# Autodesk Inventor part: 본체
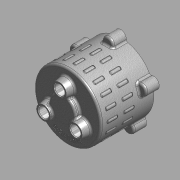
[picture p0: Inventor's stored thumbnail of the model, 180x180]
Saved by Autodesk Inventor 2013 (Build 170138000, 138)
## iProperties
Created: 2015-11
Part Number: 본체
Document SubType Name: 모델링
Designer: mdu
Material: 알루미늄 6061
Density: 1 g/cm^3
변환 표준: STEP AP214IS
파일 이름: C:\Users\SeoGD\Desktop\?쒗뿕\紐몄껜.stp
전처리기: Build: 253, Release: 2010 SP1 - Date: Wed 07/29/2009
전송 단위: 밀리미터
불확실성: 0.01
Author: mdu
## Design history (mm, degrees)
sketch "스케치2"
  geometry: C1 r 50 at (0, 0); 1 further point
  constraints: 1 centre point, 1 coincident
  dimensions: "d9" = 100 diameter of C1
extrude "돌출2" new body sketch "스케치2" distance "d10" = 80; taper "d11" = 0 deg
feature "쉘1" dims "d12" = 5
sketch "스케치3" dims "d13" = 55
  geometry: C1 r 7.5 at (0, 27.5); C2 r 12.5 at (0, 27.5); 2 further points
  constraints: 2 centre point, 2 coincident, 2 vertical alignment, 2 other
  dimensions: "d14" = 15 diameter of C1; "d15" = 25 diameter of C2
extrude "돌출3" join sketch "스케치3" distance "d16" = 12; taper "d17" = -10 deg
hole "구멍2" diameter "d20" = 15; stored, may be unused: countersink angle "d24" = 90 deg, drill point angle "d26" = 118 deg; dims "d18" = 10, "d19" = 10, "d21" = 6, "d22" = 4, "d23" = 2, "d25" = 15
chamfer "모따기1" distance "d27" = 1; stored, may be unused: second distance "d28" = 2, angle "d29" = 45 deg
sketch "스케치4"
  geometry: L1 (0, 0)-(0, 88); L2 (0, 70)-(13.16, 70); L3 (-45, 75)-(45, 75) reference; L4 (-50, 80)-(50, 80) reference; L5 (13.16, 70)-(14.5, 75); L6 (20, 80)-(20, 88); L7 (20, 88)-(0, 88); L8 (20, 80)-(14.5, 75)
  constraints: 12 end point, 3 point on line, 2 perpendicular, 1 vertical
  dimensions: "d34" = 40 diameter of L6 L1; "d35" = 105 deg angle of L5 L3; "d36" = 5 distance between parallel lines of L2 L3; "d37" = 8 distance between parallel lines of L7 L4; "d51" = 29 diameter of L5.end L1
revolve "회전1" sketch "스케치4" stored, may be unused: angle "d38" = 90 deg
hole "구멍3" diameter "d41" = 15; stored, may be unused: countersink angle "d45" = 90 deg, drill point angle "d47" = 0 deg; dims "d39" = 10, "d40" = 10, "d42" = 6, "d43" = 22, "d44" = 13, "d46" = 15
chamfer "모따기2" distance "d48" = 1; stored, may be unused: second distance "d49" = 2, angle "d50" = 45 deg
fillet "모깎기1" dims "d52" = 3
fillet "모깎기2" dims "d53" = 3, "d72" = 0.2
sketch "스케치5"
  geometry: A1 r 50 centre (0, 0) between (50, 0) and (-8.074, 49.344) reference; A2 r 8.5 centre (0, 52) between (8.074, 49.344) and (-8.074, 49.344); 1 further point
  constraints: 5 point on circle, 1 centre point, 1 horizontal alignment
  dimensions: "d54" = 90 deg dimension on point (0, 0) A2.centre A1.start; "d55" = 52 distance of A2.centre point (0, 0); "d56" = 17 diameter of A2
extrude "돌출4" join sketch "스케치5" distance "d57" = 20; taper "d58" = 0 deg
fillet "모깎기3" dims "d59" = 3
hole "구멍4" diameter "d62" = 4.134; stored, may be unused: countersink angle "d66" = 90 deg, drill point angle "d68" = 118 deg; dims "d60" = 10, "d61" = 10, "d63" = 12, "d64" = 22, "d65" = 13, "d67" = 15
sketch "스케치6"
  geometry: C1 r 47 at (0, 0) reference; C2 r 42.5 at (0, 0); 1 further point
  constraints: 1 centre point, 1 coincident, 1 other
  dimensions: "d73" = 85 diameter of C2
feature "엠보싱1" sketch "스케치6" dims "d74" = 0.5, "d75" = 0
node "작업 평면1"
sketch "스케치7"
  geometry: A1 r 50 centre (0, 0) between (5.144, 49.735) and (-5.144, 49.735) reference; A2 r 3 centre (0, 47.916) between (2.204, 49.951) and (-2.204, 49.951); 1 further point
  constraints: 4 point on circle, 1 centre point, 1 vertical alignment
  dimensions: "d77" = 3 radius of A2
extrude "돌출5" join sketch "스케치7" distance "d79" = 15; taper "d80" = 0 deg
fillet "모깎기4" dims "d81" = 1
fillet "모깎기5" dims "d82" = 1
node "솔리드1"
node "솔리드 본체"
node "곡면 본체"
pattern_circular "원형 패턴1" dims "d31" = 360 deg
pattern_circular "원형 패턴2" dims "d70" = 360 deg
pattern_circular "원형 패턴3" dims "d84" = 360 deg
pattern_linear "직사각형 패턴1" dims "d89" = 25
node "솔리드2"
